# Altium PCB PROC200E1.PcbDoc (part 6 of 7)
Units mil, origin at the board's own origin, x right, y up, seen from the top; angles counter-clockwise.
Board outline 4163.97 x 3505.34 mil, 6 copper layers (Top Layer, GND1, SIG1, PWR, GND2, Bottom), stack 58.132 mil thick; 367 components, 387 nets, 1784 pads, 858 vias.
Unrouted connection lines stored in the file: 17.
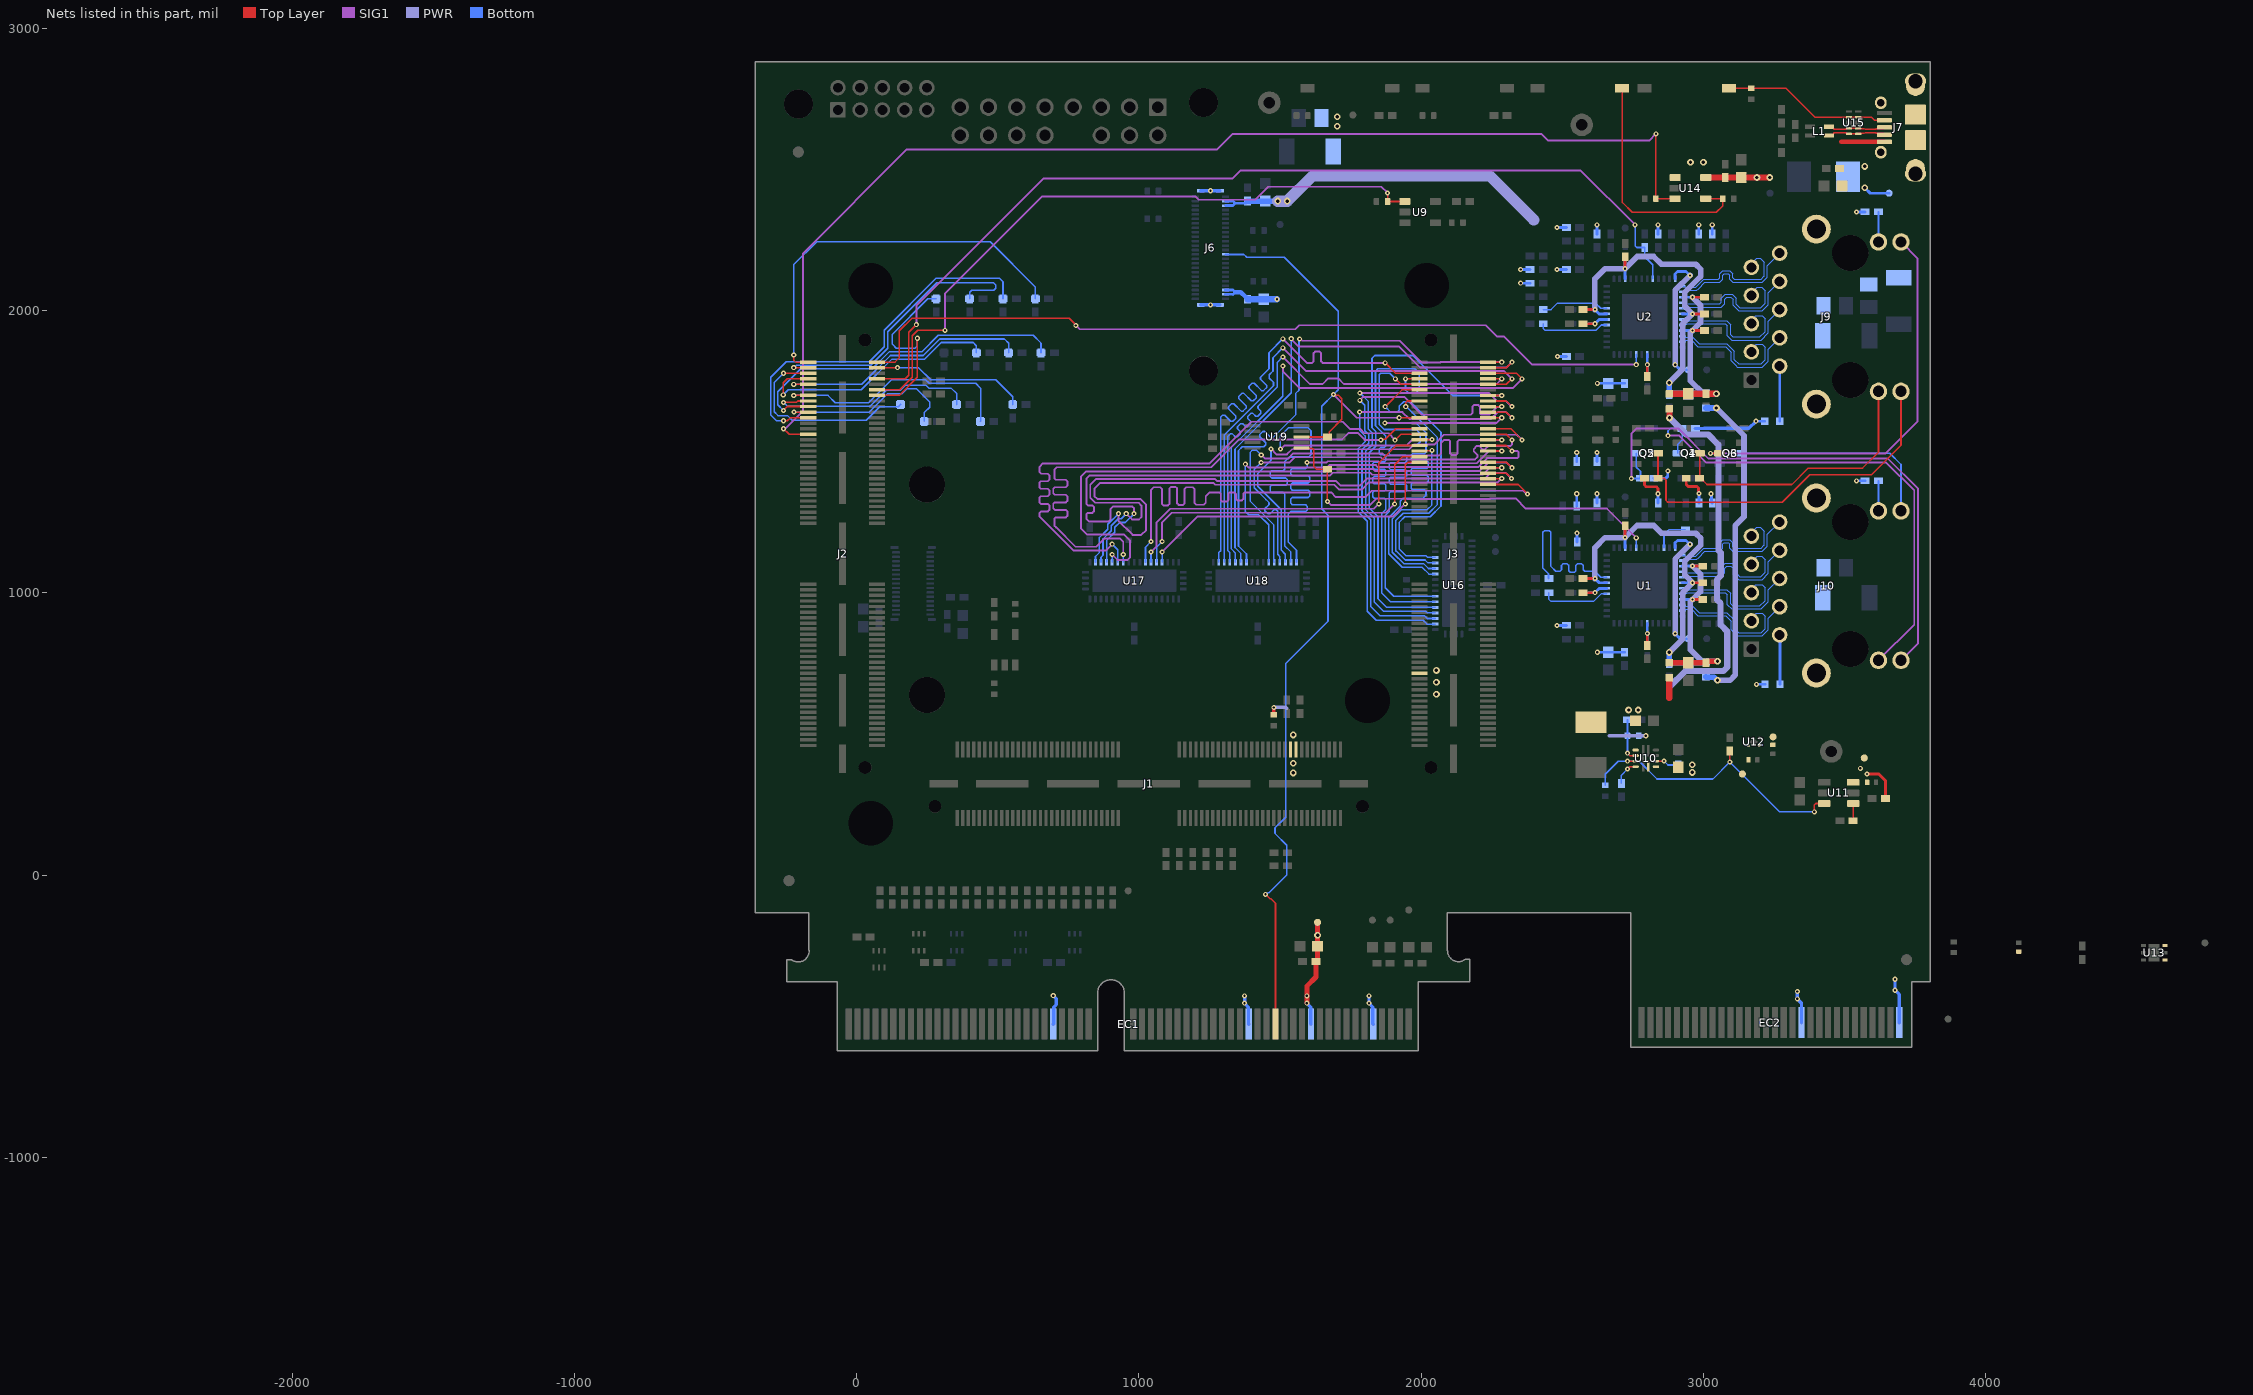
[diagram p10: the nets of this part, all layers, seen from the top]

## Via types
v1: diameter 18, hole 8, Top Layer to Bottom, tented both sides, 729 vias
v2: diameter 19.68, hole 7.87, Top Layer to Bottom, 77 vias
v3: diameter 24, hole 12, Top Layer to Bottom, tented both sides, 52 vias

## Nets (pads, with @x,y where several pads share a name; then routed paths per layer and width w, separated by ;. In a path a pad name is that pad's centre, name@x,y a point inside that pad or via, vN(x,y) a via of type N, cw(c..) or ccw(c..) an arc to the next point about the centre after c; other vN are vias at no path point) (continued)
PR0_MDIO0_MDIO: EC1.89 J3.99 J6.22 R102.1 U19.8 | length 3813.5
  Top Layer w5.66: v1(1448.39,-68.24) 1464.52,-84.37 1467.89,-84.37 1483.72,-100.21 EC1.89@1483.72,-528.32 ; U19.8@1575.63,1552.28 R102.1@1668.47,1552.28 1673.85,1557.66 1673.85,1570.02 1719,1615.17 1719,1688.09 1706.45,1700.64 1691.36,1700.64 v1(1689,1703) ; v1(1922,1620.47) J3.99@1993.48,1620.47
  SIG1 w6.66: v1(1689,1703) 1771.53,1620.47 v1(1922,1620.47)
  Bottom w5.66: J6.22@1306.63,2198.91 1372.03,2198.91 1382.11,2188.83 1514.66,2188.83 1705.81,1997.68 1705.81,1719.81 v1(1689,1703) 1647.46,1661.46 1647.46,1297.46 1669.92,1275.01 1669.92,899.59 1519.81,749.48 1519.81,204.86 1482.14,167.19 1482.14,147.65 1523.76,106.03 1523.76,-0.16 1461.78,-62.14 1457.83,-62.14 1451.73,-68.24 v1(1448.39,-68.24)
PR0_MDIO0_MDIO_ON: R105.1 U1.41 U19.6 | length 1468.6
  Top Layer w5.66: U19.6@1575.63,1512.91 1613.35,1512.91 1619.69,1506.57 1619.69,1447.31 1629.01,1437.99 R105.1@1668.47,1437.99 ; v1(1667.88,1323.59) 1667.88,1430.41 R105.1@1668.47,1430.99
  SIG1 w6.66: v1(1667.88,1323.59) 1680.07,1311.4 1819.37,1311.4 1841.43,1333.46 1951.42,1333.46 1952.16,1332.72 2243.84,1332.72 2245.52,1334.4 2335.28,1334.4 2371.26,1298.42 2658.47,1298.42 v1(2761.96,1194.93)
  Bottom w5.66: U1.41@2761.96,1159.61 v1(2761.96,1194.93)
PR0_PRU0_GPIO0: J3.102 U16.2 | length 1658.2
  Top Layer w5.66: J3.102@2236.48,1640.16 2301.77,1640.16 v1(2321.46,1620.47)
  SIG1 w6.66: v1(1782.13,1641.09) 1782.88,1640.34 1933.43,1640.34 1957.77,1616 2246.86,1616 2271.2,1640.34 2301.59,1640.34 v1(2321.46,1620.47)
  Bottom w5.66: v1(1782.13,1641.09) 1782.13,1574.77 1801.19,1555.71 1801.19,1535.28 1777.67,1511.76 1777.67,1285.09 1809.03,1253.74 1809.03,934.31 1840.49,902.84 2006.99,902.84 2020.46,889.37 U16.2@2050.02,889.37
PR0_PRU0_GPIO1: J3.104 U16.3 | length 1662
  Top Layer w5.66: J3.104@2236.48,1659.84 v1(2285.46,1659.84)
  SIG1 w6.66: v1(1782.75,1681.95) 1795.03,1694.23 1939.59,1694.23 2002.82,1631 2173,1631 2176.33,1631 2181.66,1636.33 2181.66,1659.71 2186.99,1665.04 2202.99,1665.04 2208.32,1659.71 2208.32,1636.33 2213.65,1631 2232.11,1631 2241,1631 2267.67,1657.67 2283.29,1657.67 v1(2285.46,1659.84)
  Bottom w5.66: v1@1784,1681.95 1784,1680.7 1800.36,1664.34 1800.36,1574.44 1813.85,1560.95 1813.85,1530.03 1790.33,1506.52 1790.33,1290.34 1821.69,1258.99 1821.69,951.38 1854.35,918.71 2011.99,918.71 2021.65,909.06 U16.3@2050.02,909.06
PR0_PRU0_GPIO2: J3.106 U16.4 | length 1664.8
  Top Layer w5.66: J3.106@2236.48,1679.53 2301.77,1679.53 v1(2321.46,1659.84)
  SIG1 w6.66: v1(1782.75,1707.95) 2240.7,1707.95 2269.65,1679.01 2302.29,1679.01 v1(2321.46,1659.84)
  Bottom w5.66: v1@1784,1707.95 1784,1706.7 1813.02,1677.68 1813.02,1579.69 1826.51,1566.2 1826.51,1524.79 1802.99,1501.27 1802.99,1295.58 1834.35,1264.23 1834.35,966.64 1866.16,934.82 2016.02,934.82 2022.09,928.74 U16.4@2050.02,928.74
PR0_PRU0_GPIO3: J3.108 U16.5 | length 1667.6
  Top Layer w5.66: J3.108@2236.48,1699.21 v1(2285.46,1699.21)
  Bottom w5.66: U16.5@2050.02,948.43 1877.31,948.43 1847.01,978.73 1847.01,1269.47 1815.65,1300.82 1815.65,1496.03 1839.17,1519.54 1839.17,1571.44 1825.68,1584.93 1825.68,1830.68 1836,1841 1970,1841 2111.79,1699.21 v1(2285.46,1699.21)
PR0_PRU0_GPIO4: J3.113 U16.6 | length 1659.4
  Top Layer w5.66: v1(1944.5,1758.27) J3.113@1993.48,1758.27
  Bottom w5.66: v1(1944.5,1758.27) 1944.5,1718.69 1954.19,1709 1982.67,1709 1992.59,1718.92 1992.59,1778.41 1977.32,1793.68 1846.31,1793.68 1838.34,1785.71 1838.34,1591.83 1874.83,1555.34 1874.83,1531.46 1874.83,1520.17 1869.7,1515.04 1856.13,1515.04 1851,1509.9 1851,1494.51 1856.13,1489.38 1870.02,1489.38 1875.15,1484.24 1875.15,1468.85 1870.02,1463.72 1833.45,1463.72 1828.31,1458.58 1828.31,1443.19 1833.45,1438.06 1870.02,1438.06 1875.15,1432.92 1875.15,1417.53 1870.02,1412.4 1833.45,1412.4 1828.31,1407.26 1828.31,1391.87 1833.45,1386.74 1870.02,1386.74 1875.15,1381.6 1875.15,1366.21 1870.02,1361.08 1833.45,1361.08 1828.31,1355.94 1828.31,1340.55 1833.45,1335.42 1869.7,1335.42 1874.83,1330.28 1874.83,1327.45 1874.83,1294.97 1859.67,1279.81 1859.67,999.95 1891.51,968.11 U16.6@2050.02,968.11
PR0_PRU0_GPIO5: J3.111 U16.7 | length 1666.6
  Top Layer w5.66: v1(1908.5,1758.27) 1928.19,1738.58 J3.111@1993.48,1738.58
  Bottom w5.66: v1(1908.5,1758.27) 1888.79,1777.98 1856.51,1777.98 1851,1772.47 1851,1597.08 1869.25,1578.83 1982.17,1578.83 1997,1564 1997,1535.74 1981.91,1520.66 1899.52,1520.66 1887.91,1509.05 1887.49,1508.62 1887.49,1492.2 1892.62,1487.07 1943.36,1487.07 1948.49,1481.94 1948.49,1466.54 1943.36,1461.41 1892.62,1461.41 1887.49,1456.28 1887.49,1440.88 1892.62,1435.75 1944.51,1435.75 1949.64,1430.62 1949.64,1415.22 1944.51,1410.09 1892.62,1410.09 1887.49,1404.96 1887.49,1389.56 1892.62,1384.43 1944.51,1384.43 1949.64,1379.3 1949.64,1363.9 1944.51,1358.77 1892.62,1358.77 1887.49,1353.64 1887.49,1325.15 1887.49,1288.81 1872.33,1273.64 1872.33,1018.32 1902.85,987.8 U16.7@2050.02,987.8
PR0_PRU0_GPIO6: J3.100 U16.11 | length 1656.2
  Top Layer w5.66: J3.100@2236.48,1620.47 v1(2285.46,1620.47)
  SIG1 w6.66: v1@1877.58,1601.16 2266.15,1601.16 v1(2285.46,1620.47)
  Bottom w5.66: v1(1871.26,1602.03) 1981.97,1602.03 2017.22,1566.78 2017.22,1526.79 2017.22,1498.3 2012.09,1493.17 1969.72,1493.17 1964.59,1488.03 1964.59,1472.64 1969.72,1467.51 2020.21,1467.51 2025.34,1462.37 2025.34,1446.98 2020.21,1441.85 1969.72,1441.85 1964.59,1436.71 1964.59,1421.32 1969.72,1416.19 2020.21,1416.19 2025.34,1411.05 2025.34,1395.66 2020.21,1390.53 1969.77,1390.53 1964.64,1385.39 1964.64,1370 1969.77,1364.87 2012.09,1364.87 2017.22,1359.73 2017.22,1350.96 2017.22,1345.99 2005.49,1334.26 1935.76,1334.26 1925.99,1324.49 1925.99,1307.47 1884.99,1266.46 1884.99,1138.58 1932.64,1090.92 2003.35,1090.92 2027.74,1066.54 U16.11@2050.02,1066.54
PR0_PRU0_GPIO8: J3.87 U16.12 | length 693.9
  Top Layer w5.66: J3.87@1993.48,1502.36 1994.77,1503.65 2036.72,1503.65 v1(2038,1504.93)
  Bottom w5.66: v1(2038,1504.93) 2038,1311.37 2021.69,1295.06 1931.49,1295.06 1897.65,1261.22 1897.65,1143.82 1903.32,1138.14 1937.89,1103.58 2008.6,1103.58 2025.95,1086.22 U16.12@2050.02,1086.22
PR0_PRU0_GPIO9: J3.105 U16.13 | length 895.2
  Top Layer w5.66: v1(1945.3,1659.64) 1945.3,1674.11 1950.72,1679.53 J3.105@1993.48,1679.53
  Bottom w5.66: v1(1945.3,1659.64) 1948.32,1659.64 2057.57,1550.39 2057.57,1313.04 2026.93,1282.4 1936.73,1282.4 1910.31,1255.97 1910.31,1149.07 1915.98,1143.39 1943.13,1116.24 2013.84,1116.24 2024.17,1105.91 U16.13@2050.02,1105.91
PR0_PRU0_GPIO10: J3.109 U16.14 | length 1086.4
  Top Layer w5.66: v1(1872.5,1659.64) 1931.77,1718.9 J3.109@1993.48,1718.9
  Bottom w5.66: v1(1872.5,1659.64) 1891.3,1640.84 1915.08,1640.84 1922.26,1648.03 1922.26,1661.81 1937.92,1677.47 1961.31,1677.47 2070.23,1568.55 2070.23,1307.79 2032.18,1269.74 1941.98,1269.74 1922.97,1250.73 1922.97,1154.31 1945.33,1131.94 2016.04,1131.94 2022.39,1125.59 U16.14@2050.02,1125.59
PR0_PRU0_GPIO11: J3.114 U18.4 | length 1809.5
  Top Layer w5.66: J3.114@2236.48,1758.27 v1(2285.46,1758.27)
  SIG1 w6.66: v1(1510,1836.01) 1606.07,1739.94 1651,1739.94 1671.06,1760 1705.73,1760 1725.79,1739.94 2267.13,1739.94 v1(2285.46,1758.27)
  Bottom w5.66: U18.4@1322,1108 1322,1143.26 1314.98,1150.29 1314.98,1539.02 1314.98,1554.09 1323.96,1563.07 1331.21,1563.07 1341.09,1553.19 1348.35,1553.19 1359.24,1564.08 1359.24,1571.33 1349.36,1581.21 1349.36,1588.47 1360.25,1599.36 1367.5,1599.36 1377.38,1589.48 1384.64,1589.48 1395.53,1600.37 1395.53,1607.62 1385.65,1617.5 1385.65,1624.76 1396.53,1635.64 1403.79,1635.64 1413.67,1625.77 1420.93,1625.77 1431.81,1636.65 1431.81,1643.91 1421.94,1653.79 1421.94,1661.05 1441.74,1680.85 1490,1729.11 1490,1816.01 v1(1510,1836.01)
PR0_PRU0_GPIO12: J3.116 U18.5 | length 1810.5
  Top Layer w5.66: J3.116@2236.48,1777.95 2337.77,1777.95 v1(2357.46,1758.27)
  SIG1 w6.66: v1(1510,1804.02) 1510,1785.07 1568.8,1726.28 2325.47,1726.28 v1(2357.46,1758.27)
  Bottom w5.66: U18.5@1341.69,1108 1341.69,1141.48 1327.64,1155.53 1327.64,1514.57 1510,1696.94 v1(1510,1804.02)
PR0_PRU0_GPIO13: J3.118 U18.6 | length 1810.6
  Top Layer w5.66: J3.118@2236.48,1797.64 2301.77,1797.64 v1(2321.46,1817.32)
  SIG1 w6.66: v1@1537.68,1900.67 1565.11,1873.24 1921.35,1873.24 1995.6,1798.99 2303.13,1798.99 v1(2321.46,1817.32)
  Bottom w5.66: U18.6@1361.37,1108 1361.37,1139.7 1340.3,1160.78 1340.3,1509.33 1539.71,1708.75 v1(1539.71,1900.67)
PR0_PRU0_GPIO14: J3.120 U18.7 | length 1806.5
  Top Layer w5.66: J3.120@2236.48,1817.32 v1(2285.46,1817.32)
  SIG1 w6.66: v1(1569.43,1899.43) 1572.5,1899.43 1578.91,1893.01 1924.31,1893.01 1999.99,1817.32 2000.96,1817.32 2002.07,1816.22 2068.05,1816.22 2069.16,1817.32 v1(2285.46,1817.32)
  Bottom w5.66: U18.7@1381.06,1108 1381.06,1137.92 1352.95,1166.02 1352.95,1504.08 1366.44,1517.56 1442.2,1517.56 1447.26,1522.62 1449.26,1524.63 1449.26,1531.88 1427.71,1553.43 1427.71,1560.69 1438.6,1571.58 1445.86,1571.58 1467.4,1550.03 1474.66,1550.03 1533.32,1608.68 1555,1630.37 1555,1706.13 1567.07,1718.19 1567.07,1897.07 v1(1569.43,1899.43)
PR0_PRU0_GPIO15: J3.115 U18.2 | length 1805.6
  Top Layer w5.66: v1(1872.5,1814.88) 1909.43,1777.95 J3.115@1993.48,1777.95
  SIG1 w6.66: v1(1510,1899.99) 1595.11,1814.88 1610,1814.88 1613.33,1814.88 1618.66,1820.21 1618.66,1849.21 1623.99,1854.55 1639.99,1854.55 1645.32,1849.21 1645.32,1820.21 1650.65,1814.88 1743,1814.88 v1(1872.5,1814.88)
  Bottom w5.66: U18.2@1282.63,1108 1282.63,1142.51 1289.44,1149.32 1289.44,1603.55 1289.44,1622.69 1296.39,1629.64 1303.65,1629.64 1325.56,1607.73 1332.82,1607.73 1343.7,1618.62 1343.7,1625.88 1317.47,1652.11 1317.47,1659.37 1328.35,1670.26 1335.61,1670.26 1361.85,1644.02 1369.1,1644.02 1379.99,1654.91 1379.99,1662.17 1353.76,1688.4 1353.76,1695.66 1364.64,1706.55 1371.9,1706.55 1398.14,1680.31 1405.39,1680.31 1416.28,1691.2 1416.28,1698.46 1390.04,1724.69 1390.04,1731.95 1400.93,1742.83 1408.19,1742.83 1434.42,1716.6 1441.68,1716.6 1452.57,1727.49 1452.57,1734.74 1430.66,1756.65 1430.66,1763.91 1449.88,1783.12 1460.75,1794 1460.75,1850.74 v1(1510,1899.99)
PR0_PRU0_GPIO16: J3.112 U18.3 | length 1808.2
  Top Layer w5.66: J3.112@2236.48,1738.58 2301.77,1738.58 v1(2321.46,1758.27)
  SIG1 w6.66: v1(1510,1868) 1592.67,1785.33 2294.39,1785.33 v1(2321.46,1758.27)
  Bottom w5.66: U18.3@1302.32,1108 1302.32,1559.33 1476.7,1733.72 1476.7,1745.81 1462,1760.51 1462,1773.04 1474.92,1785.96 1474.92,1832.92 v1(1510,1868)
PR0_PRU1_GPIO0: J3.78 U17.2 | length 2196
  Top Layer w5.66: J3.78@2236.48,1403.94 2237,1404.46 2284.93,1404.46 v1(2285.46,1404.99)
  SIG1 w6.66: v1(927.22,1280.63) 927.22,1255.59 977.81,1205 1007.94,1205 1025.23,1222.3 1025.23,1312.33 1004.82,1332.74 852.26,1332.74 842,1343 842,1369.29 861.76,1389.04 1264.59,1389.04 1270.73,1382.9 1692.45,1382.9 1708.81,1366.54 1790.67,1366.54 1815.11,1390.98 2271.45,1390.98 v1(2285.46,1404.99)
  Bottom w5.66: U17.2@845.97,1108 845.97,1129.02 860.02,1143.07 860.02,1195.9 889.31,1225.2 889.31,1242.71 v1(927.22,1280.63)
PR0_PRU1_GPIO1: J3.80 U17.3 | length 2190.2
  Top Layer w5.66: J3.80@2236.48,1423.62 2301.77,1423.62 v1(2320.41,1404.99)
  SIG1 w6.66: v1(955.09,1280.42) 975.68,1259.82 1000.27,1259.82 1009.04,1268.59 1009.04,1309.2 999.16,1319.08 926.16,1319.08 926.08,1319 844.98,1319 827.66,1336.32 827.66,1382.95 847.42,1402.7 1270.25,1402.7 1276.39,1396.56 1698.11,1396.56 1714.47,1380.2 1782.73,1380.2 1807.17,1404.64 2226.08,1404.64 2246.41,1424.98 2300.42,1424.98 v1(2320.41,1404.99)
  Bottom w5.66: U17.3@865.65,1108 865.65,1126.44 872.68,1133.46 872.68,1190.66 901.97,1219.95 901.97,1237.47 926.75,1262.24 936.92,1262.24 v1(955.09,1280.42)
PR0_PRU1_GPIO2: J3.82 U17.4 | length 2188
  Top Layer w5.66: J3.82@2236.48,1443.31 v1(2285.46,1443.31)
  SIG1 w6.66: v1(982.95,1280.62) 982.7,1280.86 982.7,1299.54 976.82,1305.42 947.74,1305.42 947.66,1305.34 907.66,1305.34 899.18,1296.86 899.18,1259.22 892.08,1252.12 823.98,1252.12 823.01,1253.09 814,1262.11 814,1277.75 819.33,1283.08 834.92,1283.08 840.25,1288.42 840.25,1304.41 834.92,1309.74 819.33,1309.74 814,1315.08 814,1324.98 814,1404.71 825.66,1416.36 1677.17,1416.36 1686.19,1425.38 1818.94,1425.38 1826.02,1418.3 2217.98,1418.3 2242.99,1443.31 v1(2285.46,1443.31)
  Bottom w5.66: U17.4@885.34,1108 885.34,1185.41 914.63,1214.71 914.63,1232.22 931.67,1249.26 951.59,1249.26 v1(982.95,1280.62)
PR0_PRU1_GPIO3: J3.84 U17.5 | length 2190.8
  Top Layer w5.66: J3.84@2236.48,1462.99 2301.77,1462.99 v1(2321.46,1443.31)
  SIG1 w6.66: v1(905.02,1135.53) 924.2,1116.36 959.36,1116.36 968.62,1125.62 968.62,1184.76 947.29,1206.09 816.82,1206.09 794.57,1228.34 794.57,1410.94 813.65,1430.02 1671.51,1430.02 1680.53,1439.04 1829.05,1439.04 1836.13,1431.96 2207.85,1431.96 2237.53,1461.64 2303.13,1461.64 v1(2321.46,1443.31)
  Bottom w5.66: U17.5@905.24,1108.22 v1@905.24,1135.32
PR0_PRU1_GPIO4: J3.93 U17.6 | length 2187.9
  Top Layer w5.66: v1(1907.25,1540.82) 1907.59,1540.82 1928.19,1561.42 J3.93@1993.48,1561.42
  SIG1 w6.66: v1(905.24,1172.32) 882.45,1149.53 769.05,1149.53 659.9,1258.68 648.34,1270.24 648.34,1283.34 653.68,1288.67 677.49,1288.67 682.82,1294 682.82,1310 677.49,1315.33 652.38,1315.33 647.05,1320.66 647.05,1336.66 652.38,1341.99 677.49,1341.99 682.82,1347.32 682.82,1363.32 677.49,1368.65 652.38,1368.65 647.05,1373.98 647.05,1389.98 652.38,1395.31 677.39,1395.31 682.72,1400.64 682.72,1416.64 677.39,1421.97 653.68,1421.97 648.34,1427.3 648.34,1441.61 648.34,1446.86 659.92,1458.44 1250.09,1458.44 1398.03,1606.37 1721.54,1606.37 1747.01,1580.91 1783.58,1580.91 1799.14,1565.34 1884.9,1565.34 1907.25,1542.98 v1(1907.25,1540.82)
  Bottom w5.66: v1(905.24,1172.32) 924.71,1152.85 U17.6@924.71,1108
PR0_PRU1_GPIO5: J3.95 U17.7 | length 2190.8
  Top Layer w5.66: v1(1857,1541.73) 1859.36,1544.09 1872.75,1544.09 1909.76,1581.1 J3.95@1993.48,1581.1
  SIG1 w6.66: v1(944.39,1135.53) 944.39,1181.42 933.39,1192.43 877.24,1192.43 848,1163.19 775.26,1163.19 706.45,1232 700.3,1238.15 700.3,1261.99 705.63,1267.32 741.04,1267.32 746.37,1272.65 746.37,1288.65 741.04,1293.98 701.81,1293.98 696.48,1299.31 696.48,1315.31 701.81,1320.64 741.04,1320.64 746.37,1325.97 746.37,1341.97 741.04,1347.3 701.81,1347.3 696.48,1352.63 696.48,1368.63 701.81,1373.96 741.04,1373.96 746.37,1379.29 746.37,1395.29 741.04,1400.62 705.63,1400.62 700.3,1405.95 700.3,1420 700.3,1435.86 709.21,1444.78 1255.75,1444.78 1354.24,1543.27 1719.17,1543.27 1742.67,1566.76 1774.5,1566.76 1799.52,1541.73 v1(1857,1541.73)
  Bottom w5.66: U17.7@944.61,1108.22 v1@944.61,1135.32
PR0_PRU1_GPIO6: J3.76 U17.11 | length 2191
  Top Layer w5.66: J3.76@2236.48,1384.25 2236.88,1383.85 2343.9,1383.85 2377,1350.75 v1(2377,1350)
  SIG1 w6.66: v1(1043.03,1181.78) 1043.03,1365.11 1046.29,1368.36 1051.92,1374 1076.28,1374 1081.61,1368.67 1081.61,1315.36 1086.94,1310.03 1102.94,1310.03 1108.27,1315.36 1108.27,1370.05 1113.6,1375.38 1129.6,1375.38 1134.93,1370.05 1134.93,1316.73 1140.26,1311.4 1156.26,1311.4 1161.59,1316.73 1161.59,1368.67 1166.92,1374 1183,1374 1191.38,1374 1196.74,1368.64 1196.74,1319.02 1203.58,1312.19 1229,1312.19 1236.6,1319.79 1236.6,1341.6 1250.58,1355.58 1254.71,1355.58 1284.7,1355.58 1290.04,1350.25 1290.04,1328.72 1295.37,1323.39 1311.36,1323.39 1316.7,1328.72 1316.7,1350.25 1322.03,1355.58 1338.02,1355.58 1343.36,1350.25 1343.36,1332.85 1348.69,1327.52 1364.68,1327.52 1370.02,1332.85 1370.02,1350.25 1375.35,1355.58 1424,1355.58 1681.14,1355.58 1697.49,1339.22 1801.99,1339.22 1824.49,1361.72 2362.21,1361.72 2373.93,1350 v1(2377,1350)
  Bottom w5.66: U17.11@1023.13,1108 1023.13,1161.88 v1(1043.03,1181.78)
PR0_PRU1_GPIO8: J3.89 U17.12 | length 1278.8
  Top Layer w5.66: v1(1850.17,1315.13) 1850.31,1315.27 1850.31,1460.48 1911.87,1522.05 J3.89@1993.48,1522.05
  SIG1 w6.66: v1(1042.82,1145) 1062.67,1164.85 1062.67,1250 1110.41,1297.74 1832.78,1297.74 v1(1850.17,1315.13)
  Bottom w5.66: U17.12@1042.82,1108 v1(1042.82,1145)
PR0_PRU1_GPIO9: J3.85 U17.13 | length 1239
  Top Layer w5.66: v1(1906.05,1315.13) 1906.05,1454.01 1934.72,1482.68 J3.85@1993.48,1482.68
  SIG1 w6.66: v1(1082.4,1181.78) 1082.4,1249.89 1116.25,1283.74 1874.66,1283.74 v1(1906.05,1315.13)
  Bottom w5.66: U17.13@1062.5,1108 1062.5,1161.88 v1(1082.4,1181.78)
PR0_PRU1_GPIO10: J3.83 U17.14 | length 1161
  Top Layer w5.66: v1(1943.82,1315.13) 1943.82,1453.45 1953.37,1462.99 J3.83@1993.48,1462.99
  SIG1 w6.66: v1(1082.19,1145) 1207.27,1270.08 1898.77,1270.08 v1(1943.82,1315.13)
  Bottom w5.66: U17.14@1082.19,1108 v1(1082.19,1145)
PR0_PRU1_GPIO11: J3.90 U18.11 | length 1533
  Top Layer w5.66: J3.90@2236.48,1522.05 2301.77,1522.05 v1(2321.46,1502.36)
  SIG1 w6.66: v1(1377,1456) 1389.32,1443.68 1665.85,1443.68 1674.87,1452.7 1839.48,1452.7 1846.56,1445.62 2202.19,1445.62 2233.9,1477.33 2341.1,1477.33 2345,1481.23 2345,1498.46 2341.1,1502.36 v1(2321.46,1502.36)
  Bottom w5.66: v1(1377,1456) 1377,1288.48 1388.65,1276.83 1423.99,1276.83 1459.8,1241.03 U18.11@1459.8,1108
PR0_PRU1_GPIO12: J3.92 U18.12 | length 1528.5
  Top Layer w5.66: J3.92@2236.48,1541.73 v1(2285.46,1541.73)
  SIG1 w6.66: v1(1433.35,1488.74) 1434.07,1488.74 1447.14,1475.67 1528.51,1475.67 1546.84,1494 1862.33,1494 1869.73,1486.6 2064.18,1486.6 2071.33,1493.75 2071.33,1531.58 2072.55,1532.8 2081.48,1541.73 2097.21,1541.73 2102.54,1536.4 2102.54,1494.23 2107.87,1488.9 2123.87,1488.9 2129.2,1494.23 2129.2,1536.4 2134.53,1541.73 2177.29,1541.73 v1(2285.46,1541.73)
  Bottom w5.66: v1(1433.35,1488.74) 1417.49,1504.6 1400.78,1504.6 1394.95,1498.77 1394.95,1323.77 1478.25,1240.48 1478.25,1109.23 U18.12@1479.48,1108
PR0_PRU1_GPIO13: J3.94 U18.13 | length 1528
  Top Layer w5.66: J3.94@2236.48,1561.42 2301.77,1561.42 v1(2321.46,1541.73)
  SIG1 w6.66: v1(1433.02,1462.01) 1534.16,1462.01 1552.49,1480.34 1856.67,1480.34 1864.07,1472.94 2044,1472.94 2190.73,1472.94 2196.75,1478.95 2199.1,1481.31 2199.1,1488.85 2186.18,1501.78 2186.18,1509.32 2197.49,1520.63 2205.03,1520.63 2217.96,1507.7 2225.5,1507.7 2234.7,1516.91 2238.49,1520.69 2317.56,1520.69 2321.46,1524.59 v1(2321.46,1541.73)
  Bottom w5.66: v1(1433.02,1462.01) 1408.51,1437.5 1408.51,1372.1 1450.31,1330.3 1460.82,1319.78 1460.82,1312.52 1446.09,1297.79 1446.09,1290.54 1456.98,1279.65 1464.24,1279.65 1478.97,1294.38 1486.23,1294.38 1488.23,1292.38 1491.49,1289.12 1491.49,1136.53 1499.17,1128.85 U18.13@1499.17,1108
PR0_PRU1_GPIO14: J3.96 U18.14 | length 1532.7
  Top Layer w5.66: J3.96@2236.48,1581.1 2318.09,1581.1 v1(2357.46,1541.73)
  SIG1 w6.66: v1(1468.08,1510) 1487.3,1490.78 1524.3,1490.78 1542.35,1508.83 1957.41,1508.83 1973.95,1525.37 2045.8,1525.37 2080.49,1560.06 2339.13,1560.06 v1(2357.46,1541.73)
  Bottom w5.66: v1(1468.08,1510) 1468.08,1469.73 1421.35,1423 1421.35,1377.16 1504.15,1294.36 1504.15,1151.6 1518.85,1136.89 U18.14@1518.85,1108
PR0_PRU1_GPIO15: J3.91 U18.15 | length 1524
  Top Layer w5.66: J3.91@1993.48,1541.73 1994.47,1542.72 2037.22,1542.72 v1(2038.21,1543.7)
  SIG1 w6.66: v1(1502,1510) 1503.87,1510 1516.36,1522.49 1948.58,1522.49 1969.79,1543.7 v1(2038.21,1543.7)
  Bottom w5.66: v1(1502,1510) 1501,1511 1501,1556 1530,1585 1599,1585 1609.74,1574.26 1609.74,1489.12 1602.04,1481.42 1532.69,1481.42 1524.75,1473.48 1516.81,1465.54 1516.81,1437.73 1511.67,1432.6 1469.89,1432.6 1464.76,1427.46 1464.76,1412.07 1469.89,1406.94 1520.78,1406.94 1525.91,1401.8 1525.91,1386.41 1520.78,1381.28 1469.89,1381.28 1464.76,1376.14 1464.76,1360.75 1469.89,1355.62 1511.67,1355.62 1516.81,1350.48 1516.81,1315.79 1516.81,1166.05 1538.54,1144.32 U18.15@1538.54,1108
PR0_PRU1_GPIO16: J3.88 U18.16 | length 1529.5
  Top Layer w5.66: J3.88@2236.48,1502.36 v1(2285.46,1502.36)
  SIG1 w6.66: v1(1595.74,1462.01) 1664.86,1462.01 1669.21,1466.36 1847.99,1466.36 1855.07,1459.28 2196.54,1459.28 2239.62,1502.36 v1(2285.46,1502.36)
  Bottom w5.66: U18.16@1558.22,1108 1558.22,1151.12 1529.47,1179.88 1529.47,1279.43 1538.03,1288 1590.93,1288 1595.74,1292.8 1595.74,1304.16 1595.74,1306.99 1590.6,1312.13 1543.7,1312.13 1538.57,1317.26 1538.57,1332.65 1543.7,1337.79 1599.83,1337.79 1604.97,1342.92 1604.97,1358.31 1599.83,1363.45 1543.7,1363.45 1538.57,1368.58 1538.57,1383.97 1543.7,1389.11 1599.83,1389.11 1604.97,1394.24 1604.97,1409.63 1599.83,1414.77 1543.7,1414.77 1538.57,1419.9 1538.57,1435.29 1543.7,1440.43 1590.6,1440.43 1595.74,1445.56 v1(1595.74,1462.01)
R_ICSSM_MII0_RXCLK: R4.2 U1.32 | length 627.6
  Bottom w5.66: R4.2@2452.74,1050.91 2451.03,1052.61 2451.03,1067.89 2431.07,1087.86 2431.07,1214.24 2436.69,1219.87 2454.21,1219.87 2459.68,1214.39 2459.68,1093.54 2477,1076.23 2489.11,1076.23 2491.94,1076.23 2497.07,1081.36 2497.07,1097.39 2502.2,1102.52 2517.6,1102.52 2522.73,1097.39 2522.73,1078.22 2527.86,1073.09 2543.26,1073.09 2548.39,1078.22 2548.39,1097.39 2553.52,1102.52 2568.92,1102.52 2574.05,1097.39 2574.05,1081.36 2579.18,1076.23 2612.92,1076.23 2615.56,1076.23 2636.51,1055.28 U1.32@2657.63,1055.28
R_ICSSM_MII0_RXER: R3.1 U1.46 | length 128.5
  Bottom w5.66: U1.46@2860.39,1159.61 2860.39,1205.97 2878,1223.58 R3.1@2935.19,1223.58
R_ICSSM_MII0_TXCLK: R1.2 U1.29 | length 242.7
  Bottom w5.66: R1.2@2452.74,1000.6 2452.74,976.75 2459.84,969.64 2610.84,969.64 2637.42,996.23 U1.29@2657.63,996.23
R_PHY1_RGMII1_RXC: R59.2 U2.32 | length 242.1
  Bottom w5.66: R59.2@2432.74,2003.66 2459.92,2003.66 2482.92,2026.66 2617.88,2026.66 2636.51,2008.04 U2.32@2657.63,2008.04
R_PHY1_RGMII1_TXC: R57.2 U2.29 | length 252.4
  Bottom w5.66: R57.2@2432.74,1953.35 2432.74,1936.76 2439.76,1929.74 2618.91,1929.74 2638.15,1948.98 U2.29@2657.63,1948.98
RGMII1_ETH1_CLK: J2.1 U2.20 | length 2928.5
  Top Layer w5.66: J2.1@71.48,1817.52 136.08,1817.52 150.77,1832.2 150.77,1928.23 195.58,1973.04 752.96,1973.04 776.45,1949.55 v1(776.45,1947.37)
  SIG1 w6.66: v1(776.45,1947.37) 776.66,1947.37 789.98,1934.04 1554.03,1934.04 1568.18,1948.2 2228.8,1948.2 2268.34,1908.66 2292.66,1908.66 2392.81,1808.51 v1(2761.96,1808.51)
  Bottom w5.66: v1(2761.96,1808.51) U2.20@2761.96,1844.65
RGMII1_INTn: J2.7 R60.1 U2.44 | length 3434.1
  Top Layer w5.66: J2.7@71.48,1758.47 171.75,1758.47 184.2,1770.92 184.2,1922.97 v1(211.43,1950.2)
  SIG1 w6.66: v1(211.43,1950.2) 211.43,2016.84 662.92,2468.33 1331.66,2468.33 1359.66,2496.33 2565.56,2496.33 v1(2758,2303.89)
  Bottom w5.66: v1(2758,2303.89) 2758,2229.4 2763.82,2223.58 R60.1@2791.95,2223.58 2791.95,2191.17 2821.02,2162.1 U2.44@2821.02,2112.37
RGMII1_RD0: J2.20 R28.1 R29.1 | length 662.1
  Top Layer w5.66: v1(-222.32,1640.35) J2.20@-171.52,1640.35
  Bottom w5.66: v1(-222.32,1640.35) 44.35,1640.35 109.51,1705.51 160.63,1705.51 178.09,1722.97 212,1722.97 258.44,1676.53 258.44,1657.8 239.54,1638.9 R28.1@239.54,1607.25
RGMII1_RD1: J2.18 R30.1 R32.1 | length 1230.4
  Top Layer w5.66: v1@-260.15,1646.36 -246.47,1660.04 J2.18@-171.52,1660.04
  Bottom w5.66: v1(-258.99,1646.36) -279.48,1666.85 -279.48,1712.68 -198.31,1793.85 54.9,1793.85 114.67,1853.62 230.84,1853.62 289.39,1912.17 625.83,1912.17 653,1885 R32.1@653,1850.07
RGMII1_RD2: J2.16 R33.1 R34.1 | length 790.1
  Top Layer w5.66: v1(-258.99,1674.73) -213.55,1674.73 -208.56,1679.73 J2.16@-171.52,1679.73
  Bottom w5.66: v1(-258.99,1674.73) -258.7,1674.73 -245.05,1661.08 47.17,1661.08 104.27,1718.17 155.38,1718.17 172.84,1735.63 245.35,1735.63 255.49,1725.49 334.51,1725.49 354.02,1705.98 R34.1@354.02,1667.25
RGMII1_RD3: J2.14 R35.1 R36.1 | length 886.2
  Top Layer w5.66: v1@-220.75,1699.41 J2.14@-171.52,1699.41
  Bottom w5.66: v1(-222.99,1699.41) -101.38,1699.41 -75.71,1673.74 41.93,1673.74 123.62,1755.43 243.45,1755.43 256.73,1742.15 421.85,1742.15 439,1725 439,1607.74 R35.1@438.51,1607.25
RGMII1_RST: J2.11 R86.2 U9.1 | length 2380.8
  Top Layer w5.66: J2.11@71.48,1719.1 152.31,1719.1 196.86,1763.64 196.86,1910.97 215.89,1930 v1(313.2,1930) ; v1(1880.91,2417) R86.2@1880.91,2386.55 U9.1@1942.3,2386.55
  SIG1 w6.66: v1(313.2,1930) 313.2,2060.66 656.89,2404.35 1200.14,2404.35 1211.78,2392.7 1412.15,2392.7 1458.1,2438.65 1859.26,2438.65 v1(1880.91,2417)
RGMII1_RX_CTL: J2.13 R26.1 R27.1 | length 675.7
  Top Layer w5.66: J2.13@71.48,1699.41 150.53,1699.41 214.69,1763.57 v1(214.69,1902.09)
  Bottom w5.66: v1(214.69,1902.09) 214.69,1874.96 206.29,1866.56 140.44,1866.56 126.67,1880.33 126.67,1916.51 251.91,2041.75 R27.1@281.66,2041.75
RGMII1_RXC: J2.22 R24.1 R25.1 | length 1348.5
  Top Layer w5.66: v1(-258.99,1609.67) -258.91,1609.75 -245.66,1609.75 -234.74,1620.67 J2.22@-171.52,1620.67
  Bottom w5.66: v1(-258.99,1609.67) -284.17,1609.67 -304.8,1630.3 -304.8,1763.61 -249.23,1819.17 44.41,1819.17 97.47,1872.24 97.47,1930.57 282.17,2115.27 505.08,2115.27 518.51,2101.84 R24.1@518.51,2041.75
RGMII1_TD0: J2.8 R47.1 R48.1 | length 928.6
  Top Layer w5.66: v1(-260.26,1701.63) -260.26,1744.42 -246.22,1758.47 J2.8@-171.52,1758.47
  Bottom w5.66: v1(-260.26,1701.63) -242.75,1719.14 16,1719.14 125.16,1828.3 241.33,1828.3 299.87,1886.85 412.84,1886.85 424.02,1875.66 R47.1@424.02,1850.07
RGMII1_TD1: J2.6 R49.1 R50.1 | length 720.7
  Top Layer w5.66: v1(-258.99,1778.15) J2.6@-171.52,1778.15
  Bottom w5.66: v1(-258.99,1778.15) -292.14,1745 -292.14,1641.16 -279.05,1628.07 -245.33,1628.07 -228.81,1611.56 33.46,1611.56 81.34,1659.44 147.24,1659.44 R49.1@155.05,1667.25
RGMII1_TD2: J2.4 R51.1 R52.1 | length 1062.7
  Top Layer w5.66: v1(-222.99,1797.84) J2.4@-171.52,1797.84
  Bottom w5.66: v1(-222.99,1797.84) -222.18,1797.84 -213.5,1806.51 49.65,1806.51 110.13,1866.99 110.13,1925.33 283.84,2099.03 484.46,2099.03 492.7,2090.8 492.7,2079.22 485.48,2072 407.39,2072 400.09,2064.7 R51.1@400.09,2041.75
RGMII1_TD3: J2.2 R53.1 R54.1 | length 1391.2
  Top Layer w5.66: v1(-222.99,1842.88) -222.99,1823.99 -216.52,1817.52 J2.2@-171.52,1817.52
  Bottom w5.66: v1(-222.99,1842.88) -222.99,2163.01 -142,2244 473,2244 633,2084 R54.1@633,2041.75
RGMII1_TX_CTL: J2.3 R45.1 R46.1 | length 551.5
  Top Layer w5.66: J2.3@71.48,1797.84 v1(144.29,1797.81)
  Bottom w5.66: v1(144.29,1797.81) 218.97,1797.81 261.97,1754.81 492.51,1754.81 553,1694.32 R45.1@553,1667.25
RGMII1_TXC: J2.10 R37.1 R38.1 | length 920.2
  Top Layer w5.66: v1(-222.99,1738.78) J2.10@-171.52,1738.78
  Bottom w5.66: v1(-222.99,1738.78) 17.73,1738.78 119.91,1840.96 236.08,1840.96 294.63,1899.51 523.49,1899.51 538.51,1884.49 R37.1@538.51,1850.07
RJ45_1_LED1_GREEN: J9.11 R112.2 | length 106.4
  Bottom w5.66: J9.11@3620.29,2243.26 R112.2@3620.29,2349.67
RJ45_1_LED1_YELLOW: J9.12 Q3.3 | length 1472
  Top Layer w5.66: v1(3025,1494.31) Q3.3@3057.1,1494.31
  SIG1 w6.66: v1(3025,1494.31) 3645.31,1494.31 3758,1607 3758,2185.47 J9.12@3700.21,2243.26
RJ45_1_LED2_GREEN: J9.13 Q1.3 R108.1 | length 994.4
  Top Layer w5.66: Q1.3@2986.43,1494.31 R108.1@2986.43,1405.81 2990.37,1405.81 3012.47,1383.71 3313.71,1383.71 3372,1442 3564,1442 3620.29,1498.29 J9.13@3620.29,1713.73
RJ45_1_LED2_YELLOW: J9.14 Q2.3 R110.1 | length 1301.3
  Top Layer w5.66: Q2.3@2838.99,1494.31 R110.1@2838.99,1405.81 2860.92,1405.81 2867.49,1399.24 2867.49,1327.51 2874,1321 3279,1321 3376.57,1418.57 3595.87,1418.57 3700.21,1522.92 J9.14@3700.21,1713.73
RJ45_1_VCC: FB5.2 J9.2 | length 195.3
  Bottom w10: FB5.2@3270.29,1608.19 J9.2@3270.29,1803.49
RJ45_2_LED1_GREEN: J10.11 R118.2 | length 106.4
  Bottom w5.66: J10.11@3620.29,1290.5 R118.2@3620.29,1396.92
RJ45_2_LED1_YELLOW: J10.12 Q6.3 | length 747
  Bottom w5.66: Q6.3@3133.87,1494.31 3660.69,1494.31 3700.21,1454.79 J10.12@3700.21,1290.5
RJ45_2_LED2_GREEN: J10.13 Q4.3 R115.1 | length 1771.2
  SIG1 w6.66: v1(2874.72,1556.84) 2915.2,1556.84 3010.31,1461.72 3647.96,1461.72 3746.96,1362.72 3746.96,887.64 J10.13@3620.29,760.97
  Bottom w5.66: v1(2874.72,1556.84) 2874.72,1573.46 2883.7,1582.44 R115.1@2924.42,1582.44 2924.42,1541.42 2909.66,1526.66 Q4.3@2909.66,1494.31
RJ45_2_LED2_YELLOW: J10.14 Q5.3 R117.1 | length 2030.6
  SIG1 w6.66: v1(2744.59,1405.25) 2744.59,1563.22 2764.19,1582.81 2910.58,1582.81 3017.41,1475.98 3653.02,1475.98 3760.62,1368.38 3760.62,821.38 J10.14@3700.21,760.97
  Bottom w5.66: v1(2744.59,1405.25) 2776.42,1405.25 R117.1@2776.98,1405.81 2776.98,1430.53 2762.22,1445.3 Q5.3@2762.22,1494.31
RJ45_2_VCC: FB6.2 J10.2 | length 174.8
  Bottom w10: FB6.2@3271.49,675.92 J10.2@3271.49,850.74
RJ45_ETH1_D0_N: J9.10 U2.2 | length 468.7
  Bottom w4: U2.2@2925.35,2067.09 2932.43,2067.09 2936.78,2071.43 2976.74,2071.43 2983.18,2077.88 3005.18,2099.87 3048,2099.87 3057.78,2099.87 3069.02,2111.11 3069.02,2125.79 3073.82,2130.59 3088.22,2130.59 3093.02,2125.79 3093.02,2111.11 3104.27,2099.87 3131,2099.87 3208.71,2099.87 3225.35,2116.5 3226.48,2117.64 3226.48,2159.69 J9.10@3270.29,2203.49
RJ45_ETH1_D0_P: J9.9 U2.1 | length 471.8
  Bottom w4: U2.1@2925.35,2086.78 2932.43,2086.78 2936.78,2082.43 2972.18,2082.43 3000.62,2110.87 3048,2110.87 3053.22,2110.87 3058.02,2115.67 3058.02,2130.34 3069.27,2141.59 3092.78,2141.59 3104.02,2130.34 3104.02,2115.67 3108.82,2110.87 3131,2110.87 3204.16,2110.87 3214.35,2121.06 3215.48,2122.19 3215.48,2171.76 3202.27,2184.97 3188.97,2184.97 3170.29,2166.29 J9.9@3170.29,2153.49
RJ45_ETH1_D1_N: J9.8 U2.5 | length 469.6
  Bottom w4: U2.5@2925.35,2008.04 2932.43,2008.04 2936.78,2012.38 3063.07,2012.38 3075.12,2024.43 3075.12,2039.54 3082.44,2046.86 3097.68,2046.86 3105,2039.54 3105,2018.74 3124.51,1999.23 3208.08,1999.23 3230.21,2021.36 3230.21,2063.41 J9.8@3270.29,2103.49
RJ45_ETH1_D1_P: J9.7 U2.4 | length 471.9
  Bottom w4: U2.4@2925.35,2027.72 2932.43,2027.72 2936.78,2023.38 3058.51,2023.38 3064.12,2028.98 3064.12,2044.1 3077.88,2057.86 3102.23,2057.86 3116,2044.1 3116,2023.29 3129.06,2010.23 3203.52,2010.23 3219.21,2025.92 3219.21,2069.54 3206.74,2082 3190,2082 3170.29,2062.29 J9.7@3170.29,2053.49
RJ45_ETH1_D2_N: J9.6 U2.8 | length 461.1
  Bottom w4: U2.8@2925.35,1948.98 2928.07,1951.71 2940.61,1951.71 2942.39,1953.49 2994.54,1953.49 3077.8,1953.49 3085.12,1946.16 3085.12,1910.16 3099.61,1895.68 3204.52,1895.68 3229.69,1920.84 3229.69,1962.89 J9.6@3270.29,2003.49
RJ45_ETH1_D2_P: J9.5 U2.7 | length 463.9
  Bottom w4: U2.7@2925.35,1968.67 2928.07,1965.94 2940.61,1965.94 2942.06,1964.49 2989.98,1964.49 3082.36,1964.49 3096.12,1950.72 3096.12,1914.72 3104.16,1906.68 3199.97,1906.68 3218.69,1925.4 3218.69,1970.31 3208,1981 3186,1981 3170.29,1965.29 J9.5@3170.29,1953.49
RJ45_ETH1_D3_N: J9.4 U2.11 | length 471.2
  Bottom w4: U2.11@2925.35,1889.93 2932.43,1889.93 2936.78,1894.27 2958.57,1894.27 2980.8,1872.04 3078.88,1872.04 3098.7,1852.22 3098.7,1821.8 3105.14,1815.36 3114.19,1806.31 3120.63,1799.87 3208.71,1799.87 3230.22,1821.38 3230.22,1863.43 J9.4@3270.29,1903.49
RJ45_ETH1_D3_P: J9.3 U2.10 | length 473.3
  Bottom w4: U2.10@2925.35,1909.61 2932.43,1909.61 2936.78,1905.27 2963.13,1905.27 2985.36,1883.04 3083.44,1883.04 3109.7,1856.77 3109.7,1826.36 3125.19,1810.87 3204.16,1810.87 3219.22,1825.94 3219.22,1869.29 3208.02,1880.5 3186.5,1880.5 3170.29,1864.29 J9.3@3170.29,1853.49
RJ45_ETH2_D0_N: J10.10 U1.2 | length 468.7
  Bottom w4: U1.2@2925.35,1114.34 2932.43,1114.34 2936.78,1118.68 2976.74,1118.68 2983.18,1125.12 3005.18,1147.11 3048,1147.11 3057.78,1147.11 3069.02,1158.36 3069.02,1173.03 3073.82,1177.83 3088.22,1177.83 3093.02,1173.03 3093.02,1158.36 3104.27,1147.11 3131,1147.11 3208.71,1147.11 3225.35,1163.75 3226.48,1164.88 3226.48,1206.93 J10.10@3270.29,1250.74
RJ45_ETH2_D0_P: J10.9 U1.1 | length 471.8
  Bottom w4: U1.1@2925.35,1134.02 2932.43,1134.02 2936.78,1129.68 2972.18,1129.68 3000.62,1158.11 3048,1158.11 3053.22,1158.11 3058.02,1162.91 3058.02,1177.59 3069.27,1188.83 3092.78,1188.83 3104.02,1177.59 3104.02,1162.91 3108.82,1158.11 3131,1158.11 3204.16,1158.11 3214.35,1168.3 3215.48,1169.44 3215.48,1219 3202.27,1232.21 3188.97,1232.21 3170.29,1213.53 J10.9@3170.29,1200.74
RJ45_ETH2_D1_N: J10.8 U1.5 | length 469.6
  Bottom w4: U1.5@2925.35,1055.28 2932.43,1055.28 2936.78,1059.62 3063.07,1059.62 3075.12,1071.67 3075.12,1086.79 3082.44,1094.11 3097.68,1094.11 3105,1086.79 3105,1065.98 3124.51,1046.48 3208.08,1046.48 3230.21,1068.6 3230.21,1110.65 J10.8@3270.29,1150.74
RJ45_ETH2_D1_P: J10.7 U1.4 | length 471.9
  Bottom w4: U1.4@2925.35,1074.97 2932.43,1074.97 2936.78,1070.62 3058.51,1070.62 3064.12,1076.23 3064.12,1091.34 3077.88,1105.11 3102.23,1105.11 3116,1091.34 3116,1070.54 3129.06,1057.48 3203.52,1057.48 3219.21,1073.16 3219.21,1116.78 3206.74,1129.24 3190,1129.24 3170.29,1109.53 J10.7@3170.29,1100.74
RJ45_ETH2_D2_N: J10.6 U1.8 | length 461.1
  Bottom w4: U1.8@2925.35,996.23 2928.07,998.95 2940.61,998.95 2942.39,1000.73 2994.54,1000.73 3077.8,1000.73 3085.12,993.41 3085.12,957.41 3099.61,942.92 3204.52,942.92 3229.69,968.09 3229.69,1010.13 J10.6@3270.29,1050.74
RJ45_ETH2_D2_P: J10.5 U1.7 | length 463.9
  Bottom w4: U1.7@2925.35,1015.91 2928.07,1013.19 2940.61,1013.19 2942.06,1011.73 2989.98,1011.73 3082.36,1011.73 3096.12,997.96 3096.12,961.96 3104.16,953.92 3199.97,953.92 3218.69,972.64 3218.69,1017.56 3208,1028.24 3186,1028.24 3170.29,1012.53 J10.5@3170.29,1000.74
RJ45_ETH2_D3_N: J10.4 U1.11 | length 471.2
  Bottom w4: U1.11@2925.35,937.17 2932.43,937.17 2936.78,941.51 2958.57,941.51 2980.8,919.28 3078.88,919.28 3098.7,899.46 3098.7,869.05 3105.14,862.6 3114.19,853.56 3120.63,847.11 3208.71,847.11 3230.22,868.62 3230.22,910.67 J10.4@3270.29,950.74
RJ45_ETH2_D3_P: J10.3 U1.10 | length 473.3
  Bottom w4: U1.10@2925.35,956.85 2932.43,956.85 2936.78,952.51 2963.13,952.51 2985.36,930.28 3083.44,930.28 3109.7,904.02 3109.7,873.6 3125.19,858.11 3204.16,858.11 3219.22,873.18 3219.22,916.54 3208.02,927.75 3186.5,927.75 3170.29,911.53 J10.3@3170.29,900.74
SHIELD2: C119.2 C120.2 J9.15 J9.16 J10.15 J10.16 R114.1 R121.1
SHIELD5: C61.2 C108.2 J6.49 J6.50 J6.51 J6.52 J7.6 J7.7 J7.8 J7.9 J7.10 J7.11 R84.1 R94.1 | length 135.4
  Bottom w12: J6.51@1219.42,2020.36 v1(1253.28,2020.36) J6.49@1287.14,2020.36 ; J6.52@1219.42,2424.69 v1(1253.28,2424.69) J6.50@1287.14,2424.69
  other v3: 1703,2653 1703,2686.86
USB0_DRVVBUS_SW: R89.1 SW1.2 U14.4 | length 871.3
  Top Layer w5.66: SW1.2@2711.74,2788 2713,2786.74 2713,2383 2748,2348 3046,2348 3068.5,2370.5 R89.1@3068.5,2396.67 U14.4@3008.16,2396.67
USB0_VBUS_OC: J2.28 R88.2 U14.3 | length 4264.2
  Top Layer w5.66: v1(-258.99,1581.3) -239.3,1561.61 J2.28@-171.52,1561.61 ; v1(2831.83,2626.19) R88.2@2831.83,2396.67 U14.3@2899.89,2396.67
  SIG1 w6.66: v1(-258.99,1581.3) -256.82,1583.47 -250.89,1583.47 -190,1644.36 -190,2203.18 178.11,2571.3 1277.12,2571.3 1332,2626.19 2425.36,2626.19 2449.53,2602.02 2807.66,2602.02 v1(2831.83,2626.19)
USBMICROAB_1_ID: J7.4 R91.2 SW2.1 U15.4 U15.7 | length 597.2
  Top Layer w5.66: SW2.1@3091,2788 R91.2@3170,2788 3293,2788 3395.73,2685.27 U15.7@3515.66,2685.27 U15.4@3548.54,2685.27 3595.26,2685.27 3606.09,2674.44 J7.4@3641.15,2674.44
USBMICROAB_DM: J7.2 L1.4 U15.1 U15.10 | length 207.4
  Top Layer w5: L1.4@3444.46,2620.31 3454.31,2620.31 3464.45,2630.44 3504.24,2630.44 3508.48,2626.21 U15.10@3515.66,2626.21 U15.1@3548.54,2626.21 3549.97,2627.65 3570.2,2627.65 3573,2630.44 3610.15,2630.44 3611.96,2628.63 3635.78,2628.63 J7.2@3641.15,2623.26
USBMICROAB_DP: J7.3 L1.1 U15.2 U15.9 | length 207.4
  Top Layer w5: L1.1@3444.46,2651.8 3454.31,2651.8 3464.45,2641.66 3504.24,2641.66 3508.48,2645.9 U15.9@3515.66,2645.9 U15.2@3548.54,2645.9 3549.97,2644.46 3570.2,2644.46 3573,2641.66 3610.15,2641.66 3611.96,2643.48 3635.78,2643.48 J7.3@3641.15,2648.85
VBUS_MICRO_AB_5V0: C102.2 C103.1 D1.2 J7.1 TP16.1 U14.1 | length 247.4
  Top Layer w15.75: 3487.67,2597.67 J7.1@3641.15,2597.67
  Bottom w10: v3(3572,2435) 3572.18,2435 3591.18,2416 TP16.1@3658,2416
  other v3: 3572,2511 2954.14,2526 3000,2526
VDD_2V5_EN: R87.2 U10.6 | length 92
  Top Layer w5.66: v1(2731,375.48) 2739.47,383.95 U10.6@2759.91,383.95
  Bottom w5.66: R87.2@2709.63,324.77 2709.63,354.11 v1(2731,375.48)
VDD_2V5_FB: R128.2 R129.1 U10.4 | length 151.4
  Top Layer w5.66: v1(2731,431.8) 2739.47,423.32 U10.4@2759.91,423.32
  Bottom w5.66: v1(2731,431.8) R128.2@2731,493.74 R129.1@2731,550.74
VDD_2V5_PG: R85.1 R133.2 U10.5 U11.3 | length 1051.9
  Top Layer w5.66: v1@2731.16,403.64 U10.5@2759.91,403.64 ; v1(3093.71,400.24) R85.1@3093.71,439.2 ; v1(3393,224) 3393,248.21 3398.39,253.6 U11.3@3428.29,253.6
  Bottom w5.66: R133.2@2652.63,318.52 2652.63,357.63 2698.48,403.48 v1(2731,403.48) 2772.53,403.48 2835.7,340.32 3033.79,340.32 v1(3093.71,400.24) 3269.95,224 v1(3393,224)
VDD_2V5_SS: C77.1 U10.9 | length 84.9
  Top Layer w5.66: U10.9@2831.76,403.64 v1@2860.51,403.64
  Bottom w5.66: v1(2860.67,403.8) 2874.61,389.86 C77.1@2911.03,389.86
VDD_ETH1_1V1_PHY: C31.2 C38.1 C39.1 C40.1 C41.1 C42.1 C43.1 C44.1 FB3.2 U2.6 U2.31 U2.39 | length 1547.6
  Top Layer w10: C43.1@2573.51,2003.66 v1@2615.6,2003.69 ; v1(2722.59,2148.51) C41.1@2722.6,2190.63 ; v1(2961.49,1988.35) 2961.61,1988.23 3003.39,1988.23 C39.1@3003.51,1988.11
  PWR w20: v1(2615.62,2003.71) 2615.62,2112.62 2651.51,2148.51 v1(2722.59,2148.51) 2765.55,2191.47 2823.53,2191.47 2851,2164 2973,2164 2990,2147 2990,2121 2934.49,2065.49 2934.49,2015.35 v1(2961.49,1988.35) 2926.89,1953.75 2926.89,1792.6 v3(2879,1744.71)
  Bottom w10: C42.1@2573.51,2003.66 2615.6,2003.69 2630.98,1988.35 U2.31@2657.63,1988.35 ; U2.39@2722.59,2112.37 v1(2722.59,2148.51) ; v1(2722.59,2148.51) C40.1@2722.6,2190.63 ; U2.6@2925.35,1988.35 v1(2961.49,1988.35) C44.1@3003.61,1988.34
  Bottom w20: C38.1@2879.15,1705.34 v3@2879.15,1744.56
  Bottom w22: C38.1@2879.3,1705.19 C31.2@2945.8,1705.19 FB3.2@3009.3,1705.19
VDD_ETH1_2V5_PHY: C45.2 C46.1 C47.1 C48.1 C49.1 C50.1 FB4.2 U2.3 U2.9 | length 841.3
  Top Layer w10: v1@2961.51,1929.28 C48.1@3003.51,1929.27 ; v1(2961.49,2047.41) C50.1@3003.51,2047.4
  Top Layer w22: FB4.2@2879.3,1705.19 C45.2@2945.8,1705.19 C46.1@3009.3,1705.19 v3(3046,1705.19)
  PWR w20: v1(2961.49,2047.41) 2989.85,2019.05 2989.85,1957.65 v1(2961.49,1929.3) 2953.89,1921.69 2953.89,1751.11 2999.81,1705.19 v3(3046,1705.19)
  Bottom w10: U2.9@2925.35,1929.3 v1(2961.49,1929.3) C47.1@3003.61,1929.27 ; U2.3@2925.35,2047.41 v1(2961.49,2047.41) C49.1@3003.61,2047.4
VDD_ETH2_1V1_PHY: C1.2 C2.1 C3.1 C4.1 C5.1 C6.1 C7.1 C8.1 FB1.2 U1.6 U1.31 U1.39 | length 1546.5
  Top Layer w10: C7.1@2573.53,1050.93 v1(2615.62,1050.95) ; v1(2722.59,1195.76) C5.1@2722.6,1237.87 ; v1@2961.49,1035.59 C3.1@2997.61,1035.59
  PWR w20: v1(2615.62,1050.95) 2615.62,1159.86 2651.51,1195.76 v1(2722.59,1195.76) 2765.16,1238.32 2823.92,1238.32 2851,1211.24 2973,1211.24 2990,1194.24 2990,1168.24 2934.49,1112.74 2934.49,1062.6 v1(2961.49,1035.6) 2926.89,1000.99 2926.89,836.89 v3(2879,789)
  Bottom w10: C6.1@2573.51,1050.91 v1(2615.62,1050.95) 2630.98,1035.6 U1.31@2657.63,1035.6 ; U1.39@2722.59,1159.61 v1(2722.59,1195.76) C4.1@2722.6,1237.87 ; U1.6@2925.35,1035.6 v1(2961.49,1035.6) C8.1@3003.61,1035.59
  Bottom w20: v3(2879,789) 2879.15,788.85 2879.15,749.63 C2.1@2879.3,749.48 2879.3,750.63 2881.11,752.44 C1.2@2945.8,752.44 FB1.2@3009.3,752.44
VDD_ETH2_2V5_PHY: C9.2 C10.1 C11.1 C12.1 C13.1 C14.1 FB2.2 U1.3 U1.9 | length 838.4
  Top Layer w10: v1(2961.49,976.54) C12.1@2997.61,976.53 ; v1(2961.49,1094.65) C14.1@2997.61,1094.64
  Top Layer w20: FB2.2@2879.3,752.44 C9.2@2945.8,752.44 C10.1@3009.3,752.44 3009.3,755.72 3011.11,757.53 v3@3048.92,757.53
  PWR w20: v1(2961.49,1094.65) 2989.85,1066.29 2989.85,1004.9 v1(2961.49,976.54) 2953.89,968.94 2953.89,798.35 2994.71,757.53 v3(3050,757.53)
  Bottom w10: U1.9@2925.35,976.54 v1(2961.49,976.54) C11.1@3003.61,976.53 ; U1.3@2925.35,1094.65 v1(2961.49,1094.65) C13.1@3003.61,1094.64
VDD_ETH_1V1: C100.1 FB1.1 FB3.1 TP14.1 U12.1 | length 1152.7
  PWR w20: v3(3046,1655) 3144,1557 3144,1269.44 3113,1238.44 3113,709.17 3093.83,690 v3(3050,690)
  Bottom w20: FB1.1@3009.3,702.24 3010.19,701.35 3037.57,701.35 3048.92,690 v3(3050,690)
  Bottom w22: FB3.1@3009.3,1655 v3(3046,1655)
VDD_ETH_2V5: C57.2 C58.1 C73.2 C97.1 FB2.1 FB4.1 J6.4 J6.6 L2.2 R128.1 TP13.1 U10.3 U12.4 | length 1757.3
  Top Layer w12: v1@2795.26,493 v1(2796,493.74)
  Top Layer w22: 2879.3,627.3 FB2.1@2879.3,699.29 ; FB4.1@2879.3,1652.04 2879.59,1651.75 2879.59,1620.01 v3(2879.89,1619.72)
  PWR w12: 2666,494 2666.13,493.87 2795.87,493.87 v1(2796,493.74)
  PWR w22: 2879.62,666.22 2879.62,666.37 2936.2,722.95 3070.65,722.95 3084.58,736.88 3084.58,863 3060.87,886.71 3060.87,962.68 3047.75,975.79 3047.75,1046.36 3061.79,1060.39 3061.79,1142.37 3053.03,1151.13 3053.03,1524.97 3017,1561 2938.6,1561 v3(2879.89,1619.72)
  Bottom w9.05: J6.4@1306.63,2057.17 1332.87,2057.17 ; J6.6@1306.63,2072.92 1333.32,2072.92
  Bottom w10: 1332.87,2057.17 1340.97,2065.27 1333.32,2072.92
  Bottom w12: R128.1@2770.37,493.74 2770.94,493.16 2795.43,493.16 v1(2796,493.74)
  Bottom w16: 1340.97,2065.27 1360.83,2065.27 1378.14,2047.97 1380.64,2047.97 1384.45,2044.16 C58.1@1384.45,2040.22
  Bottom w22: C58.1@1384.45,2040.22 C57.2@1441.93,2040.22 v1(1489.11,2040.22)
  other v3: 2735,585 2769,585
VDDA1_1V8: TP8.1 U2.13 U2.48 | length 507.9
  PWR w20: v1(2899.89,1808.51) 2899.89,2072.08 v1(2952.49,2124.67)
  Bottom w9.5: v1@2899.78,1808.51 U2.13@2899.78,1844.62
  Bottom w10: U2.48@2899.76,2112.37 2899.76,2130.02 2908.17,2138.44 2938.72,2138.44 v1(2952.49,2124.67) ; v1(2899.89,1808.51) 2918.2,1790.19 TP8.1@2946.49,1790.19
VDDA2_1V8: TP5.1 U1.13 U1.48 | length 507.8
  PWR w20: v1(2899.89,855.75) 2899.89,1119.32 v1(2952.49,1171.92)
  Bottom w9.5: v1@2899.78,855.75 U1.13@2899.78,891.87
  Bottom w10: U1.48@2899.76,1159.61 2899.76,1177.27 2908.17,1185.68 2938.72,1185.68 v1(2952.49,1171.92) ; v1(2899.89,855.75) 2918.2,837.44 TP5.1@2946.49,837.44
VDDIO_3V3: C15.2 C16.1 C17.1 C18.1 C19.1 C20.1 C51.2 C52.1 C53.1 C54.1 C55.1 C56.1 C59.2 C60.1 C76.1 FB5.1 FB6.1 J6.44 J6.46 R6.2 R7.2 R8.2 R9.2 R10.2 R11.2 R12.2 R13.2 R14.2 R61.2 R62.2 R63.2 R64.2 R65.2 R66.2 R67.2 R68.2 R69.2 R108.2 R110.2 R112.1 R115.2 R117.2 R118.1 R132.2 TP21.1 U1.18 U1.30 U2.18 U2.30 U11.6 | length 3281.7
  Top Layer w10: C18.1@2573.56,1000.55 v1(2615.62,1000.55) ; C54.1@2573.51,1953.35 v1(2615.62,1953.31) ; R110.2@2791.74,1405.81 2791,1405.07 2791,1381.86 2796.86,1376 2833.23,1376 2839.49,1369.74 v1(2839.49,1351.13) ; C20.1@2801.32,813.63 v1(2801.33,855.75) ; C56.1@2801.33,1766.39 v1(2801.33,1808.51) ; R108.2@2939.19,1405.81 2939.19,1383.81 2946.54,1376.46 2976.73,1376.46 2982.58,1370.6 v1@2982.58,1351.74 ; v1(3580,358) 3621.18,358 3645.18,334 R132.2@3645.18,271
  PWR w40: v3(1491.82,2387.88) v3(1525.68,2387.88) 1614.71,2476.92 2243.52,2476.92 2399.22,2321.22
  Bottom w10: J6.44@1306.63,2372.14 1332.87,2372.14 1340.97,2380.23 ; J6.46@1306.63,2387.88 1333.32,2387.88 1340.97,2380.23 ; C60.1@1384.45,2387.88 1384.45,2387.04 1377.64,2380.23 1340.97,2380.23 ; v1(2352.42,2097.11) R61.2@2385.49,2097.11 ; v1(2352.42,2145.38) R62.2@2385.49,2145.38 ; v1(2481.36,884.54) R14.2@2514.42,884.54 ; v1(2481.36,2145.38) R68.2@2514.42,2145.38 ; v1(2481.36,2294.69) R69.2@2514.42,2294.69 ; R7.2@2551.36,1308.07 v1(2551.36,1351.13) ; R12.2@2551.36,1465.24 v1(2551.36,1497.38) ; R6.2@2552.49,1179.75 v1(2552.49,1211.5) ; C17.1@2573.56,1000.55 v1(2615.62,1000.55) 2630.98,1015.91 U1.30@2657.63,1015.91 ; C53.1@2573.56,1953.31 v1(2615.62,1953.31) 2630.98,1968.67 U2.30@2657.63,1968.67 ; R11.2@2623.14,1318.07 v1(2623.14,1351.13) ; R13.2@2623.14,1465.24 v1(2623.14,1497.38) ; R63.2@2623.14,2270.82 v1(2623.14,2303.89) ; v1(2624.23,789.52) C15.2@2662.36,789.52 C16.1@2720.49,789.52 ; v1(2624.23,1742.28) C51.2@2662.36,1742.28 C52.1@2720.49,1742.28 ; C19.1@2801.32,813.63 v1(2801.33,855.75) U1.18@2801.33,891.89 ; C55.1@2801.32,1766.39 v1(2801.33,1808.51) U2.18@2801.33,1844.65 ; R117.2@2824.22,1405.81 2866.81,1405.81 2873.93,1412.93 v1(2873.93,1431.42) ; R10.2@2839.49,1318.07 v1(2839.49,1351.13) ; R65.2@2839.49,2270.82 v1(2839.49,2303.89) ; R66.2@2983.44,2270.82 v1(2983.44,2303.89) ; R9.2@2984.58,1318.67 v1(2984.58,1351.74) ; v1(3027.03,1351.13) 3028.56,1349.6 3028.56,1320.74 R8.2@3031.24,1318.07 ; R64.2@3031.24,2270.82 v1(3031.24,2303.89) ; v1(3186.8,1608.19) FB5.1@3217.14,1608.19 ; v1(3188,675.92) FB6.1@3218.34,675.92 ; v1(3542.71,1396.92) R118.1@3573.05,1396.92 ; v1(3542.71,2349.67) R112.1@3573.05,2349.67
  Bottom w12: v1(2482.69,1837.3) R67.2@2514.42,1837.3 ; R115.2@2971.67,1582.44 3002.17,1582.44 3002.54,1582.81 3161.42,1582.81 v1(3186.8,1608.19)
  Bottom w20: C60.1@1384.45,2387.88 C59.2@1447.82,2387.88 v3(1491.82,2387.88)
  other v1: 3556,378
VDDIO_3V3_CT: C75.1 U11.4 | length 61.4
  Top Layer w5.66: C75.1@3530.65,192.19 U11.4@3530.65,253.6
VMAIN_5V0_IN: C25.2 C26.1 C72.2 C78.1 C104.2 C105.2 EC1.48 EC1.84 EC1.98 EC1.112 EC2.158 EC2.180 J1.18 J1.20 J3.27 R42.1 TP1.1 U10.7 U10.8 U13.4 U13.6 U14.5 | length 1268
  Top Layer w12: R42.1@1477.92,568.4 v1(1477.95,594.05)
  Top Layer w18: v1(1594.84,-453.88) v1(1594.84,-427.85) 1594.84,-393.64 1627,-361.48 C26.1@1627,-306 ; C26.1@1633,-294.44 C25.2@1633,-253 v3(1633,-212.93) TP1.1@1633,-167.5
  Top Layer w22: U14.5@3008.16,2471.47 C105.2@3077.66,2471.47 C104.2@3133.66,2471.47 v3(3189.53,2471.47) v3(3235.39,2471.47)
  PWR w12: v1(1477.95,594.05) 1520.81,594.05 1523.84,591.02
  Bottom w12: EC1.48@696.32,-528.32 698.12,-526.53 698.12,-467.57 706.89,-458.8 706.89,-438.47 696.32,-427.9 v1(696.32,-427.41) ; v1(1374.37,-427.85) v1(1374.37,-453.88) 1374.37,-454.14 1388.12,-467.89 1388.12,-527.21 EC1.84@1389.23,-528.32 ; v1@1594.84,-454.14 1608.6,-467.89 1608.6,-527.21 EC1.98@1609.71,-528.32 ; v1(1815.32,-427.85) v1(1815.32,-453.88) 1815.32,-454.14 1829.07,-467.89 1829.07,-527.21 EC1.112@1830.18,-528.32 ; v1(3332.7,-412.5) v1(3332.7,-438.53) 3347.56,-453.4 EC2.158@3347.56,-522.97 ; v1(3679,-369.29) v1(3679,-408) 3694.02,-423.02 EC2.180@3694.02,-522.97
  other v3: 1546.79,362 2960.16,363.84 2960.16,390.84 1546.79,396.02 1546.79,496.73 2054,640.88 2054,683 2054,725.12
pads on no net: EC1.1 EC1.2 EC1.4 EC1.30 EC1.32 EC1.34 EC1.36 EC1.40 EC1.41 EC1.42 EC1.44 EC1.66 EC1.115 EC1.116 EC1.118 EC2.136 EC2.172 EC2.174 EC2.176 FID1.1 FID2.1 FID3.1 FID4.1 FID5.1 FID6.1 J1.27 J1.40 J1.42 J1.44 J1.47 J1.48 J1.52 J1.62 J1.64 J1.66 J1.68 J1.74 J1.76 J1.79 J1.80 J1.81 J1.82 J1.83 J1.84 J1.86 J1.88 J1.89 J1.90 J1.91 J1.93 J1.94 J1.95 J1.96 J1.97 J1.98 J1.99 J1.100 J1.102 J1.104 J1.MH1 J1.MH2 J2.12 J2.24 J2.27 J2.29 J2.31 J2.33 J2.35 J2.37 J2.39 J2.41 J2.42 J2.43 J2.44 J2.45 J2.46 J2.47 J2.48 J2.49 J2.51 J2.61 J2.62 J2.63 J2.64 J2.65 J2.66 J2.67 J2.68 J2.69 J2.70 J2.71 J2.72 J2.73 J2.74 J2.75 J2.76 J2.77 J2.78 J2.79 J2.80 J2.81 J2.82 J2.83 J2.84 J2.85 J2.86 J2.87 J2.88 J2.89 J2.90 J2.91 J2.92 J2.93 J2.94 J2.95 J2.96 J2.97 J2.98 J2.99 J2.100 J2.101 J2.102 J2.103 J2.104 J2.105 J2.106 J2.107 J2.108 J2.109 J2.110 J2.111 J2.112 J2.113 J2.114 J2.115 J2.116 J2.117 J2.118 J2.119 J2.120 J2.MH1 J2.MH2 J3.1 J3.2 J3.3 J3.4 J3.5 J3.6 J3.7 J3.8 J3.9 J3.10 J3.11 J3.12 J3.13 J3.14 J3.15 J3.16 J3.17 J3.18 J3.19 J3.20 J3.21 J3.22 J3.23 J3.24 J3.25 J3.26 J3.28 J3.30 J3.32 J3.34 J3.36 J3.38 J3.39 J3.40 J3.41 J3.42 J3.43 J3.44 J3.45 J3.46 J3.47 J3.48 J3.49 J3.50 J3.51 J3.52 J3.53 J3.55 J3.58 J3.60 J3.61 J3.62 J3.63 J3.64 J3.65 J3.67 J3.69 J3.70 J3.71 J3.73 J3.74 J3.75 J3.77 J3.79 J3.81 J3.86 J3.98 J3.103 J3.107 J3.110 J3.MH1 J3.MH2 J5.24 J5.25 J5.26 J5.27 J5.28 J5.29 J5.30 J8.9 J9. J10. LBL1.0 MH1.1 MH2.1 MH3.1 MH4.1 U1.14 U1.15 U1.16 U1.17 U1.19 U1.21 U1.23 U1.24 U2.14 U2.15 U2.16 U2.17 U2.19 U2.21 U2.23 U2.24 U7.5 U10.10 U13.5 U13.7@4597.11,-257.54 U13.7@4597.11,-292.97 U15.3@3548.54,2665.58 U15.5 U15.6 U15.8@3515.66,2665.58 U16.15 U16.16 U16.18 U16.19 U16.20 U16.21 U17.15 U17.16 U17.18 U17.19 U17.20 U17.21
